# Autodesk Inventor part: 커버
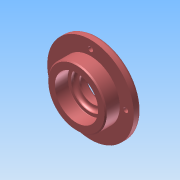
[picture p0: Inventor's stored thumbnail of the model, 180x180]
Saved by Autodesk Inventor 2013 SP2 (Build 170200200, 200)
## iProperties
Created: 2026-07
Part Number: 커버
Material: Generic
Document SubType Name: Modeling
Designer: a
Density: 1 g/cm^3
Author: a
변환 표준: STEP AP214IS
전처리기: Build: 200, Release: 2013 SP2 Update 6 - Date: Thu 07/17/2014
전송 단위: 밀리미터
불확실성: 0.01
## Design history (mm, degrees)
node "커버1"
node "솔리드1"
node "기준1"
